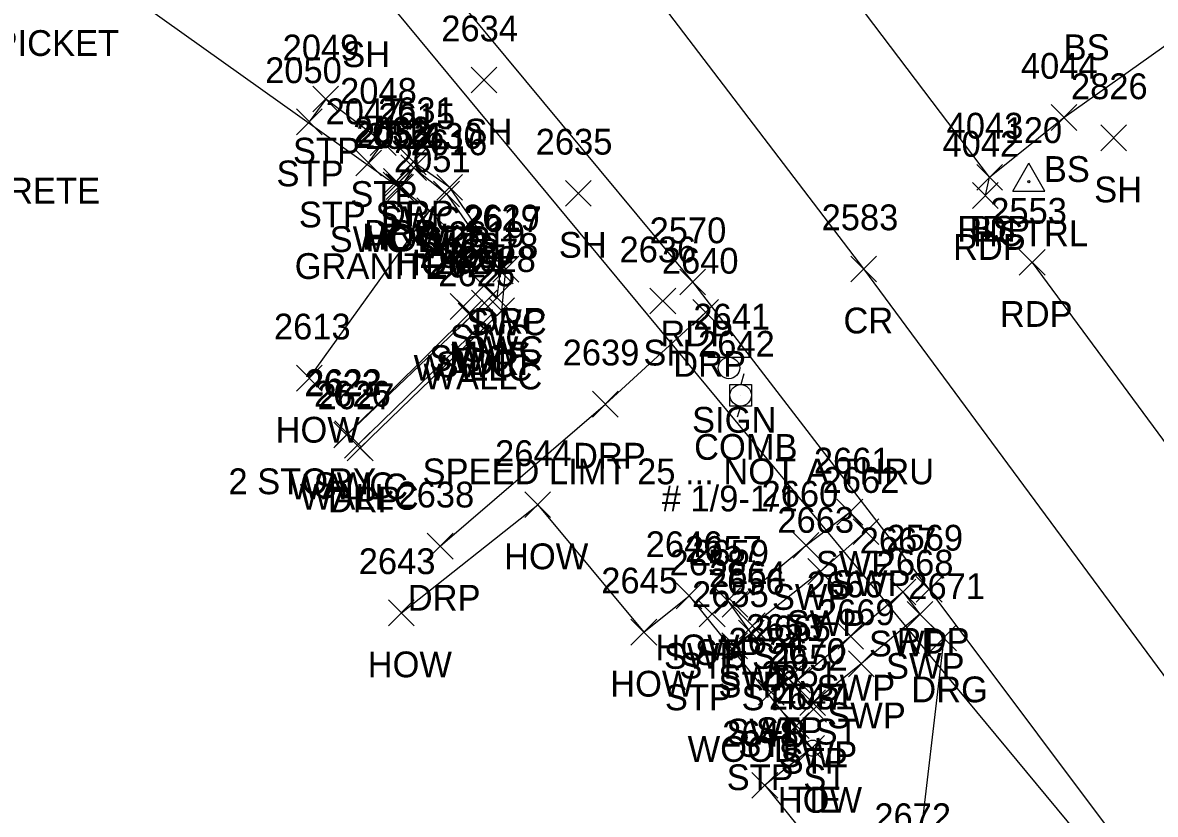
# Model space of a CAD drawing. Extents: x 1634209 to 1639641, y 608564 to 612258.
# Drawn here: x 1639153.3 to 1639241.2, y 611125 to 611186.4 of the extents above; entities that cross this region are included whole.
import ezdxf

# ---------------------------------------------------------------- set-up
doc = ezdxf.new("R2010")
doc.units = 0
for name, color, linetype in [('C_A', 7, 'Continuous'), ('C_I', 7, 'Continuous'), ('CBP', 7, 'Continuous'), ('CPH', 7, 'Continuous'), ('DCP', 7, 'Continuous'), ('L_A', 7, 'Continuous'), ('L_C', 7, 'Continuous'), ('L_I', 7, 'Continuous'), ('L_TIC', 7, 'Continuous'), ('LBC', 7, 'Continuous'), ('LBF', 7, 'Continuous'), ('LELB', 7, 'Continuous'), ('LW', 7, 'Continuous'), ('P_A', 7, 'Continuous'), ('P_I', 7, 'Continuous'), ('P_TIC', 7, 'Continuous'), ('PET', 7, 'Continuous'), ('PRC', 7, 'Continuous'), ('R_A', 7, 'Continuous'), ('R_I', 7, 'Continuous'), ('R_TIC', 7, 'Continuous'), ('RDG', 7, 'Continuous'), ('RDP', 7, 'Continuous'), ('RSW', 7, 'Continuous'), ('S_A', 7, 'Continuous'), ('S_C', 7, 'Continuous'), ('S_I', 7, 'Continuous'), ('SSGN', 7, 'Continuous'), ('U_A', 7, 'Continuous'), ('U_C', 7, 'Continuous'), ('U_I', 7, 'Continuous'), ('UP', 7, 'Continuous')]:
    doc.layers.add(name, color=color, linetype=linetype)

msp = doc.modelspace()

# ---------------------------------------------------------------- linework, layer by layer
at = {"layer": 'CBP'}
for radius in [0.625, 0.0833]:
    msp.add_circle((1639214.603, 611130.126), radius, dxfattribs=at)
at = {"layer": 'CPH'}
for p, q in [((1639230.112, 611173.325), (1639231.362, 611175.49)), ((1639232.612, 611173.325), (1639231.362, 611175.49)), ((1639231.363, 611174.047), (1639231.363, 611174.047)), ((1639230.112, 611173.325), (1639232.612, 611173.325))]:
    msp.add_line(p, q, dxfattribs=at)
msp.add_circle((1639231.363, 611174.047), 0.0833, dxfattribs=at)
at = {"layer": 'DCP'}
msp.add_lwpolyline([(1639280.744, 611068.51), (1639160.798, 611213.264)], dxfattribs=at)
at = {"layer": 'L_TIC'}
for points in [[(1639188.103, 611180.932), (1639190.103, 611182.932)], [(1639190.103, 611180.932), (1639188.103, 611182.932)], [(1639175.834, 611179.456), (1639177.834, 611181.456)], [(1639177.834, 611179.456), (1639175.834, 611181.456)], [(1639174.556, 611177.691), (1639176.556, 611179.691)], [(1639176.556, 611177.691), (1639174.556, 611179.691)], [(1639233.084, 611178.03), (1639235.084, 611180.03)], [(1639235.084, 611178.03), (1639233.084, 611180.03)], [(1639180.285, 611176.091), (1639182.285, 611178.091)], [(1639182.285, 611176.091), (1639180.285, 611178.091)], [(1639236.94, 611176.449), (1639238.94, 611178.449)], [(1639238.94, 611176.449), (1639236.94, 611178.449)], [(1639179.156, 611174.507), (1639181.156, 611176.507)], [(1639181.156, 611174.507), (1639179.156, 611176.507)], [(1639227.322, 611173.392), (1639229.322, 611175.392)], [(1639229.322, 611173.392), (1639227.322, 611175.392)], [(1639181.278, 611172.787), (1639183.278, 611174.787)], [(1639183.278, 611172.787), (1639181.278, 611174.787)], [(1639181.528, 611172.659), (1639183.528, 611174.659)], [(1639183.528, 611172.659), (1639181.528, 611174.659)], [(1639195.423, 611172.15), (1639197.423, 611174.15)], [(1639197.423, 611172.15), (1639195.423, 611174.15)], [(1639183.889, 611170.787), (1639185.889, 611172.787)], [(1639185.889, 611170.787), (1639183.889, 611172.787)], [(1639188.131, 611163.639), (1639190.131, 611165.639)], [(1639190.131, 611163.639), (1639188.131, 611165.639)], [(1639201.976, 611163.795), (1639203.976, 611165.795)], [(1639203.976, 611163.795), (1639201.976, 611165.795)], [(1639187.106, 611162.621), (1639189.106, 611164.621)], [(1639189.106, 611162.621), (1639187.106, 611164.621)], [(1639187.875, 611161.942), (1639189.875, 611163.942)], [(1639189.875, 611161.942), (1639187.875, 611163.942)], [(1639174.554, 611157.815), (1639176.554, 611159.815)], [(1639176.554, 611157.815), (1639174.554, 611159.815)], [(1639177.466, 611153.413), (1639179.466, 611155.413)], [(1639179.466, 611153.413), (1639177.466, 611155.413)], [(1639178.288, 611152.606), (1639180.288, 611154.606)], [(1639180.288, 611152.606), (1639178.288, 611154.606)], [(1639192.271, 611147.998), (1639194.271, 611149.998)], [(1639194.271, 611147.998), (1639192.271, 611149.998)], [(1639204.009, 611140.936), (1639206.009, 611142.936)], [(1639206.009, 611140.936), (1639204.009, 611142.936)], [(1639207.005, 611140.563), (1639209.005, 611142.563)], [(1639209.005, 611140.563), (1639207.005, 611142.563)], [(1639181.699, 611139.617), (1639183.699, 611141.617)], [(1639183.699, 611139.617), (1639181.699, 611141.617)], [(1639205.801, 611139.521), (1639207.801, 611141.521)], [(1639207.801, 611139.521), (1639205.801, 611141.521)], [(1639200.505, 611138.119), (1639202.505, 611140.119)], [(1639202.505, 611138.119), (1639200.505, 611140.119)], [(1639208.831, 611138.05), (1639210.831, 611140.05)], [(1639210.831, 611138.05), (1639208.831, 611140.05)], [(1639207.545, 611137.061), (1639209.545, 611139.061)], [(1639209.545, 611137.061), (1639207.545, 611139.061)], [(1639211.737, 611134.512), (1639213.737, 611136.512)], [(1639213.737, 611134.512), (1639211.737, 611136.512)], [(1639210.372, 611133.446), (1639212.372, 611135.446)], [(1639212.372, 611133.446), (1639210.372, 611135.446)], [(1639213.66, 611132.135), (1639215.66, 611134.135)], [(1639215.66, 611132.135), (1639213.66, 611134.135)], [(1639212.336, 611130.867), (1639214.336, 611132.867)], [(1639214.336, 611130.867), (1639212.336, 611132.867)], [(1639213.503, 611129.111), (1639215.503, 611131.111)], [(1639215.503, 611129.111), (1639213.503, 611131.111)], [(1639209.883, 611126.244), (1639211.883, 611128.244)], [(1639211.883, 611126.244), (1639209.883, 611128.244)]]:
    msp.add_lwpolyline(points, dxfattribs=at)
at = {"layer": 'LBC'}
for points in [[(1639184.889, 611171.787), (1639182.528, 611173.659), (1639182.278, 611173.787), (1639155.358, 611192.972), (1639133.903, 611163.404)], [(1639175.554, 611158.815), (1639184.889, 611171.787)], [(1639182.699, 611140.617), (1639193.271, 611148.998), (1639201.505, 611139.119), (1639205.009, 611141.936), (1639214.503, 611130.111), (1639210.883, 611127.244), (1639218.875, 611117.361), (1639210.188, 611110.286)]]:
    msp.add_lwpolyline(points, dxfattribs=at)
at = {"layer": 'LBF'}
for points in [[(1639180.156, 611175.507), (1639181.285, 611177.091), (1639176.834, 611180.456), (1639175.556, 611178.691)], [(1639208.545, 611138.061), (1639209.831, 611139.05), (1639208.005, 611141.563), (1639206.801, 611140.521)], [(1639213.336, 611131.867), (1639214.66, 611133.135), (1639212.737, 611135.512), (1639211.372, 611134.446)]]:
    msp.add_lwpolyline(points, dxfattribs=at)
at = {"layer": 'LELB'}
msp.add_lwpolyline([(1639228.322, 611174.392), (1639234.084, 611179.03), (1639255.187, 611194.038), (1639278.67, 611212.132)], dxfattribs=at)
at = {"layer": 'LW'}
msp.add_lwpolyline([(1639178.466, 611154.413), (1639188.106, 611163.621), (1639188.875, 611162.942), (1639179.288, 611153.606)], dxfattribs=at)
at = {"layer": 'P_TIC'}
for points in [[(1639227.322, 611173.392), (1639229.322, 611175.392)], [(1639229.322, 611173.392), (1639227.322, 611175.392)], [(1639226.993, 611171.983), (1639228.993, 611173.983)], [(1639228.993, 611171.983), (1639226.993, 611173.983)], [(1639217.548, 611166.285), (1639219.548, 611168.285)], [(1639219.548, 611166.285), (1639217.548, 611168.285)], [(1639230.623, 611166.792), (1639232.623, 611168.792)], [(1639232.623, 611166.792), (1639230.623, 611168.792)], [(1639204.296, 611165.276), (1639206.296, 611167.276)], [(1639206.296, 611165.276), (1639204.296, 611167.276)], [(1639222.626, 611141.441), (1639224.626, 611143.441)], [(1639224.626, 611141.441), (1639222.626, 611143.441)]]:
    msp.add_lwpolyline(points, dxfattribs=at)
at = {"layer": 'PET'}
for points in [[(1639227.993, 611172.983), (1639228.322, 611174.392), (1639214.901, 611192.139), (1639202.86, 611208.109), (1639190.658, 611226.999), (1639183.077, 611239.215), (1639162.79, 611271.004), (1639160.915, 611274.858), (1639160.063, 611279.394), (1639160.107, 611285.354), (1639161.856, 611291.074), (1639181.022, 611319.858), (1639203.193, 611353.293), (1639219.74, 611378.248), (1639229.459, 611393.468), (1639239.186, 611407.624), (1639252.485, 611428.758), (1639267.876, 611454.496), (1639285.596, 611485.313)], [(1639410.825, 610892.364), (1639390.458, 610919.541), (1639371.801, 610946.358), (1639349.879, 610975.696), (1639327.189, 611005.386), (1639302.754, 611038.38), (1639275.028, 611075.512), (1639248.834, 611108.817), (1639223.626, 611142.441), (1639205.296, 611166.276), (1639182.184, 611194.122), (1639165.678, 611212.038), (1639150.219, 611225.989), (1639136.405, 611234.042), (1639135.28, 611232.533), (1639130.918, 611235.275), (1639127.562, 611237.663), (1639124.139, 611238.638)], [(1639231.623, 611167.792), (1639256.202, 611134.454), (1639283.543, 611097.441), (1639314.632, 611055.995), (1639346.719, 611013.836), (1639378.41, 610971.724), (1639408.009, 610931.002), (1639426.871, 610904.613)]]:
    msp.add_lwpolyline(points, dxfattribs=at)
at = {"layer": 'PRC'}
msp.add_lwpolyline([(1639145.026, 611260.3), (1639159.742, 611243.634), (1639188.697, 611206.44), (1639218.548, 611167.285), (1639245.48, 611130.825), (1639271.83, 611094.919), (1639293.449, 611066.846), (1639319.074, 611033.054), (1639349.486, 610993.068), (1639374.145, 610959.599), (1639396.768, 610928.589), (1639419.083, 610897.866)], dxfattribs=at)
at = {"layer": 'R_TIC'}
for points in [[(1639182.622, 611174.587), (1639184.622, 611176.587)], [(1639184.622, 611174.587), (1639182.622, 611176.587)], [(1639182.659, 611174.136), (1639184.659, 611176.136)], [(1639184.659, 611174.136), (1639182.659, 611176.136)], [(1639181.312, 611173.081), (1639183.312, 611175.081)], [(1639183.312, 611173.081), (1639181.312, 611175.081)], [(1639181.638, 611172.595), (1639183.638, 611174.595)], [(1639183.638, 611172.595), (1639181.638, 611174.595)], [(1639185.45, 611172.605), (1639187.45, 611174.605)], [(1639187.45, 611172.605), (1639185.45, 611174.605)], [(1639185.197, 611172.102), (1639187.197, 611174.102)], [(1639187.197, 611172.102), (1639185.197, 611174.102)], [(1639189.799, 611166.263), (1639191.799, 611168.263)], [(1639191.799, 611166.263), (1639189.799, 611168.263)], [(1639189.366, 611166.14), (1639191.366, 611168.14)], [(1639191.366, 611166.14), (1639189.366, 611168.14)], [(1639188.089, 611164.972), (1639190.089, 611166.972)], [(1639190.089, 611164.972), (1639188.089, 611166.972)], [(1639189.111, 611164.069), (1639191.111, 611166.069)], [(1639191.111, 611164.069), (1639189.111, 611166.069)], [(1639186.489, 611163.368), (1639188.489, 611165.368)], [(1639188.489, 611163.368), (1639186.489, 611165.368)], [(1639186.998, 611162.885), (1639188.998, 611164.885)], [(1639188.998, 611162.885), (1639186.998, 611164.885)], [(1639189.481, 611163.048), (1639191.481, 611165.048)], [(1639191.481, 611163.048), (1639189.481, 611165.048)], [(1639205.291, 611162.919), (1639207.291, 611164.919)], [(1639207.291, 611162.919), (1639205.291, 611164.919)], [(1639197.522, 611155.8), (1639199.522, 611157.8)], [(1639199.522, 611155.8), (1639197.522, 611157.8)], [(1639177.542, 611153.505), (1639179.542, 611155.505)], [(1639179.542, 611153.505), (1639177.542, 611155.505)], [(1639178.502, 611152.406), (1639180.502, 611154.406)], [(1639180.502, 611152.406), (1639178.502, 611154.406)], [(1639216.475, 611147.419), (1639218.475, 611149.419)], [(1639218.475, 611147.419), (1639216.475, 611149.419)], [(1639217.726, 611145.917), (1639219.726, 611147.917)], [(1639219.726, 611145.917), (1639217.726, 611147.917)], [(1639184.703, 611144.786), (1639186.703, 611146.786)], [(1639186.703, 611144.786), (1639184.703, 611146.786)], [(1639213.072, 611144.847), (1639215.072, 611146.847)], [(1639215.072, 611144.847), (1639213.072, 611146.847)], [(1639214.211, 611142.823), (1639216.211, 611144.823)], [(1639216.211, 611142.823), (1639214.211, 611144.823)], [(1639220.6, 611141.232), (1639222.6, 611143.232)], [(1639222.6, 611141.232), (1639220.6, 611143.232)], [(1639207.567, 611140.275), (1639209.567, 611142.275)], [(1639209.567, 611140.275), (1639207.567, 611142.275)], [(1639221.919, 611139.504), (1639223.919, 611141.504)], [(1639223.919, 611139.504), (1639221.919, 611141.504)], [(1639208.916, 611138.609), (1639210.916, 611140.609)], [(1639210.916, 611138.609), (1639208.916, 611140.609)], [(1639216.541, 611137.811), (1639218.541, 611139.811)], [(1639218.541, 611137.811), (1639216.541, 611139.811)], [(1639223.755, 611137.679), (1639225.755, 611139.679)], [(1639225.755, 611137.679), (1639223.755, 611139.679)], [(1639217.365, 611135.662), (1639219.365, 611137.662)], [(1639219.365, 611135.662), (1639217.365, 611137.662)], [(1639212.413, 611134.402), (1639214.413, 611136.402)], [(1639214.413, 611134.402), (1639212.413, 611136.402)], [(1639213.599, 611132.647), (1639215.599, 611134.647)], [(1639215.599, 611132.647), (1639213.599, 611134.647)]]:
    msp.add_lwpolyline(points, dxfattribs=at)
at = {"layer": 'RDG'}
msp.add_lwpolyline([(1639224.755, 611138.679), (1639222.685, 611120.842), (1639219.384, 611117.884)], dxfattribs=at)
at = {"layer": 'RDP'}
for points in [[(1639179.502, 611153.406), (1639190.481, 611164.048), (1639190.799, 611167.263), (1639186.45, 611173.605), (1639183.622, 611175.587), (1639182.312, 611174.081)], [(1639185.703, 611145.786), (1639198.522, 611156.8), (1639206.291, 611163.919)]]:
    msp.add_lwpolyline(points, dxfattribs=at)
at = {"layer": 'RSW'}
for points in [[(1639182.638, 611173.595), (1639183.659, 611175.136), (1639186.197, 611173.102), (1639190.366, 611167.14), (1639190.111, 611165.069), (1639189.089, 611165.972), (1639187.489, 611164.368), (1639187.998, 611163.885), (1639178.542, 611154.505)], [(1639208.567, 611141.275), (1639214.072, 611145.847), (1639217.475, 611148.419), (1639218.726, 611146.917), (1639215.211, 611143.823), (1639209.916, 611139.609)], [(1639213.413, 611135.402), (1639217.541, 611138.811), (1639221.6, 611142.232), (1639222.919, 611140.504), (1639218.365, 611136.662), (1639214.599, 611133.647)]]:
    msp.add_lwpolyline(points, dxfattribs=at)
at = {"layer": 'SSGN'}
for p, q in [((1639206.455, 611160.437), (1639209.789, 611160.437)), ((1639208.102, 611159.604), (1639208.102, 611159.604))]:
    msp.add_line(p, q, dxfattribs=at)
msp.add_circle((1639208.102, 611159.604), 0.833, dxfattribs=at)
at = {"layer": 'UP'}
for p, q in [((1639209.263, 611159.151), (1639209.013, 611158.317)), ((1639208.179, 611156.651), (1639208.179, 611158.317)), ((1639208.179, 611158.317), (1639209.846, 611158.317)), ((1639209.846, 611158.317), (1639209.846, 611156.651)), ((1639209.013, 611157.484), (1639209.013, 611157.484)), ((1639209.846, 611156.651), (1639208.179, 611156.651)), ((1639208.763, 611155.817), (1639209.013, 611156.651))]:
    msp.add_line(p, q, dxfattribs=at)
msp.add_circle((1639209.013, 611157.484), 0.833, dxfattribs=at)

# ---------------------------------------------------------------- texts
at = {"layer": 'C_A'}
for s, p in [('HCTRL', (1639227.032, 611169.047)), ('TIE', (1639212.682, 611125.126))]:
    msp.add_text(s, height=2, dxfattribs=at).set_placement(p)
at = {"layer": 'C_I'}
for s, p in [('120', (1639229.481, 611177.047)), ('4031', (1639211.831, 611133.126))]:
    msp.add_text(s, height=2, dxfattribs=at).set_placement(p)
at = {"layer": 'L_A'}
for s, p in [('SH', (1639178.11, 611182.935)), ('BS', (1639234.059, 611183.476)), ('SH', (1639187.591, 611176.932)), ('STP', (1639174.29, 611175.456)), ('STP', (1639173.012, 611173.691)), ('BS', (1639232.525, 611174.03)), ('SH', (1639236.428, 611172.449)), ('STP', (1639178.742, 611172.091)), ('STP ST', (1639174.747, 611170.507)), ('BS', (1639226.763, 611169.392)), ('HOW', (1639179.664, 611168.787)), ('HOW', (1639179.914, 611168.659)), ('SH', (1639194.911, 611168.15)), ('HOW', (1639182.275, 611166.787)), ('MMF', (1639186.414, 611159.639)), ('SH', (1639201.464, 611159.795)), ('WALLC', (1639183.642, 611158.621)), ('WALLC', (1639184.411, 611157.942)), ('HOW', (1639172.94, 611153.815)), ('WALLC', (1639174.001, 611149.413)), ('WALLC', (1639174.824, 611148.606)), ('HOW', (1639190.657, 611143.998)), ('HOW', (1639202.395, 611136.936)), ('STP', (1639205.461, 611136.563)), ('HOW', (1639180.085, 611135.617)), ('STP', (1639204.257, 611135.521)), ('HOW', (1639198.891, 611134.119)), ('STP', (1639207.288, 611134.05)), ('STP ST', (1639203.135, 611133.061)), ('STP', (1639210.194, 611130.512)), ('STP', (1639208.829, 611129.446)), ('STP', (1639212.117, 611128.135)), ('STP ST', (1639207.926, 611126.867)), ('HOW', (1639211.889, 611125.111))]:
    msp.add_text(s, height=2, dxfattribs=at).set_placement(p)
at = {"layer": 'L_C'}
for s, p in [('PICKET', (1639151.146, 611183.801)), ('GRANITE   CONCRETE', (1639130.202, 611172.358)), ('GRANITE', (1639174.424, 611166.507)), ('2 STORY', (1639169.286, 611149.815)), ('WOOD', (1639204.899, 611129.061))]:
    msp.add_text(s, height=2, dxfattribs=at).set_placement(p)
at = {"layer": 'L_I'}
for s, p in [('2634', (1639185.796, 611184.932)), ('2049', (1639173.487, 611183.456)), ('4044', (1639230.745, 611182.03)), ('2050', (1639172.131, 611181.691)), ('2826', (1639234.625, 611180.449)), ('2048', (1639177.947, 611180.091)), ('2047', (1639176.818, 611178.507)), ('2053', (1639178.94, 611176.787)), ('4043', (1639224.984, 611177.392)), ('2052', (1639179.19, 611176.659)), ('2635', (1639193.116, 611176.15)), ('2051', (1639182.117, 611174.787)), ('2637', (1639185.824, 611167.639)), ('2636', (1639199.614, 611167.795)), ('2624', (1639184.799, 611166.621)), ('2625', (1639185.568, 611165.942)), ('2613', (1639172.814, 611161.815)), ('2623', (1639175.159, 611157.413)), ('2626', (1639175.926, 611156.606)), ('2644', (1639189.964, 611151.998)), ('2646', (1639201.647, 611144.936)), ('2657', (1639204.698, 611144.563)), ('2643', (1639179.392, 611143.617)), ('2658', (1639203.494, 611143.521)), ('2645', (1639198.198, 611142.119)), ('2656', (1639206.469, 611142.05)), ('2655', (1639205.238, 611141.061)), ('2653', (1639209.43, 611138.512)), ('2654', (1639208.065, 611137.446)), ('2652', (1639211.353, 611136.135)), ('2651', (1639210.596, 611134.867)), ('2647', (1639211.196, 611133.111)), ('2648', (1639207.576, 611130.244))]:
    msp.add_text(s, height=2, dxfattribs=at).set_placement(p)
at = {"layer": 'P_A'}
for s, p in [('RDP', (1639225.81, 611169.392)), ('RDP', (1639225.481, 611167.983)), ('RDP', (1639229.112, 611162.792)), ('CR', (1639216.981, 611162.285)), ('RDP', (1639202.784, 611161.276)), ('RDP', (1639221.114, 611137.441))]:
    msp.add_text(s, height=2, dxfattribs=at).set_placement(p)
at = {"layer": 'P_I'}
for s, p in [('4043', (1639224.984, 611177.392)), ('4042', (1639224.655, 611175.983)), ('2553', (1639228.364, 611170.792)), ('2583', (1639215.288, 611170.285)), ('2570', (1639201.949, 611169.276)), ('2569', (1639220.311, 611145.441))]:
    msp.add_text(s, height=2, dxfattribs=at).set_placement(p)
at = {"layer": 'R_A'}
for s, p in [('SWC', (1639181.022, 611170.136)), ('DRP', (1639181.11, 611170.587)), ('DRP', (1639179.8, 611169.081)), ('SWC ST', (1639177.134, 611168.595)), ('SWC', (1639183.559, 611168.102)), ('DRP', (1639183.938, 611168.605)), ('SWC', (1639187.729, 611162.14)), ('DRP', (1639188.287, 611162.263)), ('SWC', (1639186.452, 611160.972)), ('SWC', (1639187.473, 611160.069)), ('SWC', (1639184.852, 611159.368)), ('SWC', (1639185.361, 611158.885)), ('DRP', (1639187.97, 611159.048)), ('DRP', (1639203.78, 611158.919)), ('DRP', (1639196.01, 611151.8)), ('SWC', (1639175.904, 611149.505)), ('DRP', (1639176.991, 611148.406)), ('SWP', (1639214.837, 611143.419)), ('SWP', (1639216.088, 611141.917)), ('DRP', (1639183.191, 611140.786)), ('SWP', (1639211.434, 611140.847)), ('SWP', (1639212.573, 611138.823)), ('SWP', (1639218.962, 611137.232)), ('SWP ST', (1639203.063, 611136.275)), ('SWP', (1639220.281, 611135.504)), ('SWP', (1639207.279, 611134.609)), ('SWP', (1639214.903, 611133.811)), ('DRG', (1639222.243, 611133.679)), ('SWP', (1639215.728, 611131.662)), ('SWP ST', (1639207.909, 611130.402)), ('SWP', (1639211.961, 611128.647))]:
    msp.add_text(s, height=2, dxfattribs=at).set_placement(p)
at = {"layer": 'R_I'}
for s, p in [('2631', (1639180.882, 611178.587)), ('2615', (1639180.919, 611178.136)), ('2632', (1639179.005, 611177.081)), ('2614', (1639179.898, 611176.595)), ('2630', (1639183.056, 611176.605)), ('2616', (1639183.402, 611176.102)), ('2629', (1639187.484, 611170.263)), ('2617', (1639187.626, 611170.14)), ('2619', (1639186.342, 611168.972)), ('2618', (1639187.371, 611168.069)), ('2620', (1639184.096, 611167.368)), ('2621', (1639185.258, 611166.885)), ('2628', (1639187.174, 611167.048)), ('2640', (1639202.898, 611166.919)), ('2639', (1639195.207, 611159.8)), ('2622', (1639175.235, 611157.505)), ('2627', (1639176.195, 611156.406)), ('2661', (1639214.687, 611151.419)), ('2662', (1639215.371, 611149.917)), ('2638', (1639182.396, 611148.786)), ('2660', (1639210.631, 611148.847)), ('2663', (1639211.857, 611146.823)), ('2667', (1639218.245, 611145.232)), ('2659', (1639205.252, 611144.275)), ('2668', (1639219.565, 611143.504)), ('2664', (1639206.562, 611142.609)), ('2666', (1639214.131, 611141.811)), ('2671', (1639222.014, 611141.679)), ('2669', (1639215.003, 611139.662)), ('2665', (1639210.059, 611138.402)), ('2670', (1639211.205, 611136.647)), ('2672', (1639219.378, 611123.842))]:
    msp.add_text(s, height=2, dxfattribs=at).set_placement(p)
at = {"layer": 'S_A'}
msp.add_text('SIGN', height=2, dxfattribs=at).set_placement((1639205.24, 611154.584))
at = {"layer": 'S_C'}
msp.add_text('SPEED LIMT 25 ... NOT A THRU', height=2, dxfattribs=at).set_placement((1639184.335, 611150.584))
at = {"layer": 'S_I'}
msp.add_text('2641', height=2, dxfattribs=at).set_placement((1639205.343, 611162.584))
at = {"layer": 'U_A'}
msp.add_text('COMB', height=2, dxfattribs=at).set_placement((1639205.399, 611152.484))
at = {"layer": 'U_C'}
msp.add_text('# 1/9-1/1', height=2, dxfattribs=at).set_placement((1639202.887, 611148.484))
at = {"layer": 'U_I'}
msp.add_text('2642', height=2, dxfattribs=at).set_placement((1639205.706, 611160.484))

doc.saveas('drawing.dxf')
